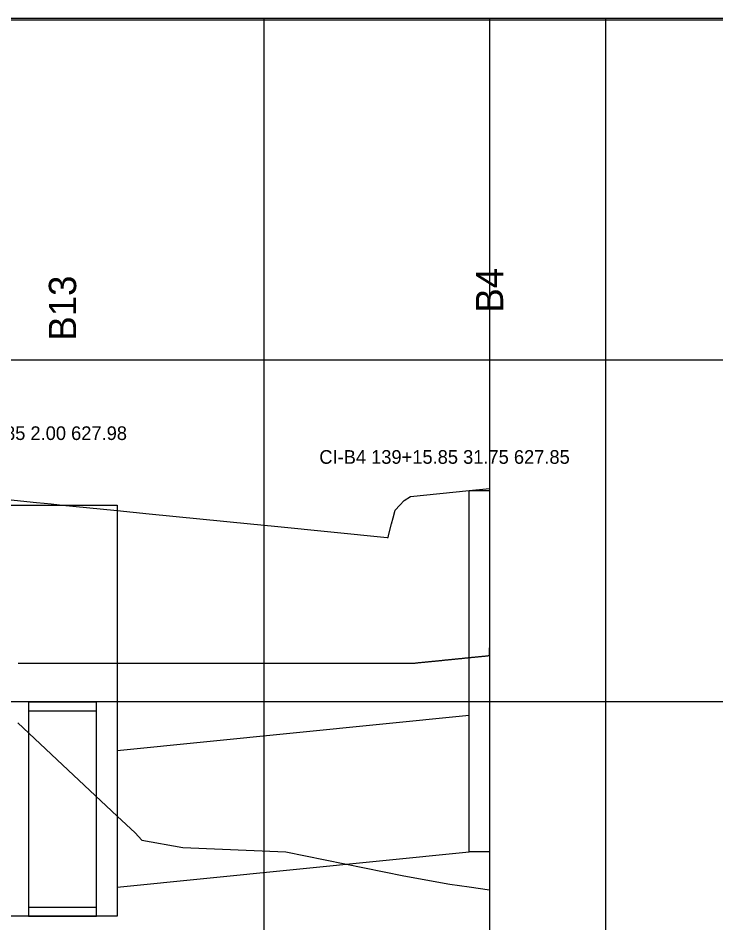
# Model space of a CAD drawing. Extents: x 2253035 to 2279930, y 13774972 to 13793443.
# Drawn here: x 2276981.4 to 2277032.5, y 13792726.4 to 13792792.6 of the extents above; entities that cross this region are included whole.
import ezdxf

# ---------------------------------------------------------------- set-up
doc = ezdxf.new("R2010")
doc.units = 0
for name, color, linetype in [('Default', 7, 'Continuous'), ('E_Utility_ATT_HH', 7, 'Continuous'), ('E_Utility_ATT_PR_PVC', 7, 'Continuous'), ('E_Utility_Telephone_Manhole Telephone_MHT_point', 7, 'Continuous'), ('E_Utility_Telephone_Telephone Pedestal_TPED_Description', 7, 'Continuous'), ('E_Utility_Water_Water Meter_WM_Description', 7, 'Continuous'), ('E_Utillity_Water_Water Line_12in', 7, 'Continuous'), ('E_Utillity_Water_Water Line_1in', 7, 'Continuous'), ('E_Utillity_Water_Water Line_4in', 7, 'Continuous'), ('E_Utillity_Water_Water Line_8in', 7, 'Continuous')]:
    doc.layers.add(name, color=color, linetype=linetype)

msp = doc.modelspace()

# ---------------------------------------------------------------- linework, layer by layer
at = {"layer": 'Default'}
for p, q in [((2276949.404, 13792767.599), (2277015.904, 13792767.599)), ((2276949.404, 13792742.599), (2277015.904, 13792742.599))]:
    msp.add_line(p, q, dxfattribs=at)
msp.add_lwpolyline([(2276949.404, 13792692.599), (2276949.404, 13792792.599), (2277015.904, 13792792.599), (2277015.904, 13792692.599)], close=True, dxfattribs=at)
at = {"layer": 'E_Utility_ATT_PR_PVC'}
msp.add_line((2276984.654, 13792745.405), (2276984.654, 13792745.405), dxfattribs=at)
for points in [[(2276984.654, 13792745.405), (2276984.705, 13792745.405), (2276984.755, 13792745.405), (2276984.805, 13792745.405), (2276984.855, 13792745.405), (2276984.905, 13792745.405), (2276984.955, 13792745.405), (2276985.005, 13792745.405), (2276985.055, 13792745.405), (2276985.105, 13792745.405), (2276985.155, 13792745.405), (2276985.206, 13792745.405), (2276985.256, 13792745.405), (2276985.306, 13792745.405), (2276985.356, 13792745.405), (2276985.406, 13792745.406), (2276985.456, 13792745.406), (2276985.506, 13792745.406), (2276985.556, 13792745.406), (2276985.606, 13792745.406), (2276985.657, 13792745.406), (2276985.707, 13792745.406), (2276985.757, 13792745.406), (2276985.807, 13792745.406), (2276985.857, 13792745.406), (2276985.907, 13792745.406), (2276985.957, 13792745.406), (2276986.007, 13792745.406), (2276986.057, 13792745.406), (2276986.108, 13792745.406), (2276986.158, 13792745.406), (2276986.208, 13792745.406), (2276986.258, 13792745.406), (2276986.308, 13792745.406), (2276986.358, 13792745.406), (2276986.408, 13792745.406), (2276986.458, 13792745.406), (2276986.508, 13792745.406), (2276986.559, 13792745.406), (2276986.609, 13792745.406), (2276986.659, 13792745.406), (2276986.709, 13792745.406), (2276986.759, 13792745.406), (2276986.809, 13792745.406), (2276986.859, 13792745.406), (2276986.909, 13792745.406), (2276986.959, 13792745.406), (2276987.01, 13792745.406), (2276987.06, 13792745.406), (2276987.11, 13792745.406), (2276987.16, 13792745.406), (2276987.21, 13792745.406), (2276987.26, 13792745.406), (2276987.31, 13792745.406), (2276987.36, 13792745.406), (2276987.41, 13792745.406), (2276987.46, 13792745.406), (2276987.511, 13792745.406), (2276987.561, 13792745.406), (2276987.611, 13792745.406), (2276987.661, 13792745.406), (2276987.711, 13792745.406), (2276987.761, 13792745.406), (2276987.811, 13792745.406), (2276987.861, 13792745.406), (2276987.911, 13792745.406), (2276987.962, 13792745.406), (2276988.012, 13792745.406), (2276988.062, 13792745.406), (2276988.112, 13792745.406), (2276988.162, 13792745.406), (2276988.212, 13792745.406), (2276988.262, 13792745.406), (2276988.312, 13792745.406), (2276988.362, 13792745.406), (2276988.413, 13792745.406), (2276988.463, 13792745.406), (2276988.513, 13792745.406), (2276988.563, 13792745.406), (2276988.613, 13792745.406), (2276988.663, 13792745.406), (2276988.713, 13792745.406), (2276988.763, 13792745.406), (2276988.813, 13792745.406), (2276988.864, 13792745.406), (2276988.914, 13792745.406), (2276988.964, 13792745.406), (2276989.014, 13792745.406), (2276989.064, 13792745.406), (2276989.114, 13792745.406), (2276989.164, 13792745.406), (2276989.214, 13792745.406), (2276989.264, 13792745.406), (2276989.315, 13792745.406), (2276989.365, 13792745.406), (2276989.415, 13792745.406), (2276989.465, 13792745.406), (2276989.515, 13792745.406), (2276989.565, 13792745.406), (2276989.615, 13792745.406), (2276989.665, 13792745.406), (2276989.715, 13792745.406), (2276989.765, 13792745.406), (2276989.816, 13792745.406), (2276989.866, 13792745.406), (2276989.916, 13792745.406), (2276989.966, 13792745.407), (2276990.016, 13792745.407), (2276990.066, 13792745.407), (2276990.116, 13792745.407), (2276990.166, 13792745.407), (2276990.216, 13792745.407), (2276990.267, 13792745.407), (2276990.317, 13792745.407), (2276990.367, 13792745.407), (2276990.417, 13792745.407), (2276990.467, 13792745.407), (2276990.517, 13792745.407), (2276990.567, 13792745.407), (2276990.617, 13792745.407), (2276990.667, 13792745.407), (2276990.718, 13792745.407), (2276990.768, 13792745.407), (2276990.818, 13792745.407), (2276990.868, 13792745.407), (2276990.918, 13792745.407), (2276990.968, 13792745.407), (2276991.018, 13792745.407), (2276991.068, 13792745.407), (2276991.118, 13792745.407), (2276991.169, 13792745.407), (2276991.219, 13792745.407), (2276991.269, 13792745.407), (2276991.319, 13792745.407), (2276991.369, 13792745.407), (2276991.419, 13792745.407), (2276991.469, 13792745.407), (2276991.519, 13792745.407), (2276991.569, 13792745.407), (2276991.62, 13792745.407), (2276991.67, 13792745.407), (2276991.72, 13792745.407), (2276991.77, 13792745.407), (2276991.82, 13792745.407), (2276991.87, 13792745.407), (2276991.92, 13792745.407), (2276991.97, 13792745.407), (2276992.02, 13792745.407), (2276992.071, 13792745.407), (2276992.121, 13792745.407), (2276992.171, 13792745.407), (2276992.221, 13792745.407), (2276992.271, 13792745.407), (2276992.321, 13792745.407), (2276992.371, 13792745.407), (2276992.421, 13792745.407), (2276992.471, 13792745.407), (2276992.521, 13792745.407), (2276992.572, 13792745.407), (2276992.622, 13792745.407), (2276992.672, 13792745.407), (2276992.722, 13792745.407), (2276992.772, 13792745.407), (2276992.822, 13792745.407), (2276992.872, 13792745.407), (2276992.922, 13792745.407), (2276992.972, 13792745.407), (2276993.023, 13792745.407), (2276993.073, 13792745.407), (2276993.123, 13792745.407), (2276993.173, 13792745.407), (2276993.223, 13792745.407), (2276993.273, 13792745.407), (2276993.323, 13792745.407), (2276993.373, 13792745.407), (2276993.423, 13792745.407), (2276993.474, 13792745.407), (2276993.524, 13792745.407), (2276993.574, 13792745.407), (2276993.624, 13792745.407), (2276993.674, 13792745.407), (2276993.724, 13792745.407), (2276993.774, 13792745.407), (2276993.824, 13792745.407), (2276993.874, 13792745.407), (2276993.925, 13792745.407), (2276993.975, 13792745.407), (2276994.025, 13792745.407), (2276994.075, 13792745.407), (2276994.125, 13792745.407), (2276994.175, 13792745.407), (2276994.225, 13792745.407), (2276994.275, 13792745.407), (2276994.325, 13792745.407), (2276994.376, 13792745.407), (2276994.426, 13792745.407), (2276994.476, 13792745.407), (2276994.526, 13792745.407), (2276994.576, 13792745.408), (2276994.626, 13792745.408), (2276994.676, 13792745.408), (2276994.726, 13792745.408), (2276994.776, 13792745.408), (2276994.826, 13792745.408), (2276994.877, 13792745.408), (2276994.927, 13792745.408), (2276994.977, 13792745.408), (2276995.027, 13792745.408), (2276995.077, 13792745.408), (2276995.127, 13792745.408), (2276995.177, 13792745.408), (2276995.227, 13792745.408), (2276995.277, 13792745.408), (2276995.328, 13792745.408), (2276995.378, 13792745.408), (2276995.428, 13792745.408), (2276995.478, 13792745.408), (2276995.528, 13792745.408), (2276995.578, 13792745.408), (2276995.628, 13792745.408), (2276995.678, 13792745.408), (2276995.728, 13792745.408), (2276995.779, 13792745.408), (2276995.829, 13792745.408), (2276995.879, 13792745.408), (2276995.929, 13792745.408), (2276995.979, 13792745.408), (2276996.029, 13792745.408), (2276996.079, 13792745.408), (2276996.129, 13792745.408), (2276996.179, 13792745.408), (2276996.23, 13792745.408), (2276996.28, 13792745.408), (2276996.33, 13792745.408), (2276996.38, 13792745.408), (2276996.43, 13792745.408), (2276996.48, 13792745.408), (2276996.53, 13792745.408), (2276996.58, 13792745.408), (2276996.63, 13792745.408), (2276996.681, 13792745.408), (2276996.731, 13792745.408), (2276996.781, 13792745.408), (2276996.831, 13792745.408), (2276996.881, 13792745.408), (2276996.931, 13792745.408), (2276996.981, 13792745.408), (2276997.031, 13792745.408), (2276997.081, 13792745.408), (2276997.132, 13792745.408), (2276997.182, 13792745.408), (2276997.232, 13792745.408), (2276997.282, 13792745.408), (2276997.332, 13792745.408), (2276997.382, 13792745.408), (2276997.432, 13792745.408), (2276997.482, 13792745.408), (2276997.532, 13792745.408), (2276997.582, 13792745.408), (2276997.633, 13792745.408), (2276997.683, 13792745.408), (2276997.733, 13792745.408), (2276997.783, 13792745.408), (2276997.833, 13792745.408), (2276997.883, 13792745.408), (2276997.933, 13792745.408), (2276997.983, 13792745.408), (2276998.033, 13792745.408), (2276998.084, 13792745.408), (2276998.134, 13792745.408), (2276998.184, 13792745.408), (2276998.234, 13792745.408), (2276998.284, 13792745.408), (2276998.334, 13792745.408), (2276998.384, 13792745.408), (2276998.434, 13792745.408), (2276998.484, 13792745.408), (2276998.535, 13792745.408), (2276998.585, 13792745.408), (2276998.635, 13792745.408), (2276998.685, 13792745.408), (2276998.735, 13792745.408), (2276998.785, 13792745.408), (2276998.835, 13792745.408), (2276998.885, 13792745.408), (2276998.935, 13792745.408), (2276998.986, 13792745.408), (2276999.036, 13792745.408), (2276999.086, 13792745.408), (2276999.136, 13792745.409), (2276999.186, 13792745.409), (2276999.236, 13792745.409), (2276999.286, 13792745.409), (2276999.336, 13792745.409), (2276999.386, 13792745.409), (2276999.437, 13792745.409), (2276999.487, 13792745.409), (2276999.537, 13792745.409), (2276999.587, 13792745.409), (2276999.637, 13792745.409), (2276999.687, 13792745.409), (2276999.737, 13792745.409), (2276999.787, 13792745.409), (2276999.837, 13792745.409), (2276999.887, 13792745.409), (2276999.938, 13792745.409), (2276999.988, 13792745.409), (2277000.038, 13792745.409), (2277000.088, 13792745.409), (2277000.138, 13792745.409), (2277000.188, 13792745.409), (2277000.238, 13792745.409), (2277000.288, 13792745.409), (2277000.338, 13792745.409), (2277000.389, 13792745.409), (2277000.439, 13792745.409), (2277000.489, 13792745.409), (2277000.539, 13792745.409), (2277000.589, 13792745.409), (2277000.639, 13792745.409), (2277000.689, 13792745.409), (2277000.739, 13792745.409), (2277000.789, 13792745.409), (2277000.84, 13792745.409), (2277000.89, 13792745.409), (2277000.94, 13792745.409), (2277000.99, 13792745.409), (2277001.04, 13792745.409), (2277001.09, 13792745.409), (2277001.14, 13792745.409), (2277001.19, 13792745.409), (2277001.24, 13792745.409), (2277001.291, 13792745.409), (2277001.341, 13792745.409), (2277001.391, 13792745.409), (2277001.441, 13792745.409), (2277001.491, 13792745.409), (2277001.541, 13792745.409), (2277001.591, 13792745.409), (2277001.641, 13792745.409), (2277001.691, 13792745.409), (2277001.742, 13792745.409), (2277001.792, 13792745.409), (2277001.842, 13792745.409), (2277001.892, 13792745.409), (2277001.942, 13792745.409), (2277001.992, 13792745.409), (2277002.042, 13792745.409), (2277002.092, 13792745.409), (2277002.142, 13792745.409), (2277002.193, 13792745.409), (2277002.243, 13792745.409), (2277002.293, 13792745.409), (2277002.343, 13792745.409), (2277002.393, 13792745.409), (2277002.443, 13792745.409), (2277002.493, 13792745.409), (2277002.543, 13792745.409), (2277002.593, 13792745.409), (2277002.643, 13792745.409), (2277002.694, 13792745.409), (2277002.744, 13792745.409), (2277002.794, 13792745.409), (2277002.844, 13792745.409), (2277002.894, 13792745.409), (2277002.944, 13792745.409), (2277002.994, 13792745.409), (2277003.044, 13792745.409), (2277003.094, 13792745.409), (2277003.145, 13792745.409), (2277003.195, 13792745.409), (2277003.245, 13792745.409), (2277003.295, 13792745.409), (2277003.345, 13792745.409), (2277003.395, 13792745.409), (2277003.445, 13792745.409), (2277003.495, 13792745.409), (2277003.545, 13792745.409), (2277003.596, 13792745.409), (2277003.646, 13792745.409), (2277003.696, 13792745.409), (2277003.746, 13792745.41), (2277003.796, 13792745.41), (2277003.846, 13792745.41), (2277003.896, 13792745.41), (2277003.946, 13792745.41), (2277003.996, 13792745.41), (2277004.047, 13792745.41), (2277004.097, 13792745.41), (2277004.147, 13792745.41), (2277004.197, 13792745.41), (2277004.247, 13792745.41), (2277004.297, 13792745.41), (2277004.347, 13792745.41), (2277004.397, 13792745.41), (2277004.447, 13792745.41), (2277004.498, 13792745.41), (2277004.548, 13792745.41), (2277004.598, 13792745.41), (2277004.648, 13792745.41), (2277004.698, 13792745.41), (2277004.748, 13792745.41), (2277004.798, 13792745.41), (2277004.848, 13792745.41), (2277004.898, 13792745.41), (2277004.948, 13792745.41), (2277004.999, 13792745.41), (2277005.049, 13792745.41), (2277005.099, 13792745.41), (2277005.149, 13792745.41), (2277005.199, 13792745.41), (2277005.249, 13792745.41), (2277005.299, 13792745.41), (2277005.349, 13792745.41), (2277005.399, 13792745.41), (2277005.45, 13792745.41), (2277005.5, 13792745.41), (2277005.55, 13792745.41), (2277005.6, 13792745.41), (2277005.65, 13792745.41), (2277005.7, 13792745.41), (2277005.75, 13792745.41), (2277005.8, 13792745.41), (2277005.85, 13792745.41), (2277005.901, 13792745.41), (2277005.951, 13792745.41), (2277006.001, 13792745.41), (2277006.051, 13792745.41), (2277006.101, 13792745.41), (2277006.151, 13792745.41), (2277006.201, 13792745.41), (2277006.251, 13792745.41), (2277006.301, 13792745.41), (2277006.352, 13792745.41), (2277006.402, 13792745.41), (2277006.452, 13792745.41), (2277006.502, 13792745.41), (2277006.552, 13792745.41), (2277006.602, 13792745.41), (2277006.652, 13792745.41), (2277006.702, 13792745.41), (2277006.752, 13792745.41), (2277006.803, 13792745.41), (2277006.853, 13792745.41), (2277006.903, 13792745.41), (2277006.953, 13792745.41), (2277007.003, 13792745.41), (2277007.053, 13792745.41), (2277007.103, 13792745.41), (2277007.153, 13792745.41), (2277007.203, 13792745.41), (2277007.254, 13792745.41), (2277007.304, 13792745.41), (2277007.354, 13792745.41), (2277007.404, 13792745.41), (2277007.454, 13792745.41), (2277007.504, 13792745.41), (2277007.554, 13792745.41), (2277007.604, 13792745.41), (2277007.654, 13792745.41), (2277007.704, 13792745.41), (2277007.755, 13792745.41), (2277007.805, 13792745.41), (2277007.855, 13792745.41), (2277007.905, 13792745.41), (2277007.955, 13792745.41), (2277008.005, 13792745.41), (2277008.055, 13792745.41), (2277008.105, 13792745.41), (2277008.155, 13792745.41), (2277008.206, 13792745.41), (2277008.256, 13792745.41), (2277008.306, 13792745.41), (2277008.356, 13792745.411), (2277008.406, 13792745.411), (2277008.456, 13792745.411), (2277008.506, 13792745.411), (2277008.556, 13792745.411), (2277008.606, 13792745.411), (2277008.657, 13792745.411), (2277008.707, 13792745.411), (2277008.757, 13792745.411), (2277008.807, 13792745.411), (2277008.857, 13792745.411), (2277008.907, 13792745.411), (2277008.957, 13792745.411), (2277009.007, 13792745.411), (2277009.057, 13792745.411), (2277009.108, 13792745.411), (2277009.158, 13792745.411), (2277009.208, 13792745.411), (2277009.258, 13792745.411), (2277009.308, 13792745.411), (2277009.358, 13792745.411), (2277009.408, 13792745.411), (2277009.458, 13792745.411), (2277009.508, 13792745.411), (2277009.559, 13792745.411), (2277009.609, 13792745.411), (2277009.659, 13792745.411), (2277009.709, 13792745.411), (2277009.759, 13792745.411), (2277009.809, 13792745.411), (2277009.859, 13792745.411), (2277009.909, 13792745.411), (2277009.959, 13792745.411), (2277010.009, 13792745.411), (2277010.06, 13792745.411), (2277010.11, 13792745.411), (2277010.16, 13792745.411), (2277010.21, 13792745.411), (2277010.26, 13792745.411), (2277010.31, 13792745.411), (2277010.36, 13792745.411), (2277010.41, 13792745.412), (2277010.46, 13792745.417), (2277010.511, 13792745.422), (2277010.561, 13792745.427), (2277010.611, 13792745.432), (2277010.661, 13792745.437), (2277010.711, 13792745.442), (2277010.761, 13792745.447), (2277010.811, 13792745.452), (2277010.861, 13792745.457), (2277010.911, 13792745.462), (2277010.962, 13792745.467), (2277011.012, 13792745.472), (2277011.062, 13792745.477), (2277011.112, 13792745.482), (2277011.162, 13792745.487), (2277011.212, 13792745.492), (2277011.262, 13792745.497), (2277011.312, 13792745.502), (2277011.362, 13792745.507), (2277011.413, 13792745.512), (2277011.463, 13792745.517), (2277011.513, 13792745.522), (2277011.563, 13792745.527), (2277011.613, 13792745.532), (2277011.663, 13792745.537), (2277011.713, 13792745.542), (2277011.763, 13792745.547), (2277011.813, 13792745.552), (2277011.864, 13792745.557), (2277011.914, 13792745.562), (2277011.964, 13792745.567), (2277012.014, 13792745.572), (2277012.064, 13792745.577), (2277012.114, 13792745.582), (2277012.164, 13792745.587), (2277012.214, 13792745.592), (2277012.264, 13792745.597), (2277012.314, 13792745.602), (2277012.365, 13792745.607), (2277012.415, 13792745.612), (2277012.465, 13792745.617), (2277012.515, 13792745.622), (2277012.565, 13792745.627), (2277012.615, 13792745.633), (2277012.665, 13792745.638), (2277012.715, 13792745.643), (2277012.765, 13792745.648), (2277012.816, 13792745.653), (2277012.866, 13792745.658), (2277012.916, 13792745.663), (2277012.966, 13792745.668), (2277013.016, 13792745.673), (2277013.066, 13792745.678), (2277013.116, 13792745.683), (2277013.166, 13792745.688), (2277013.216, 13792745.693), (2277013.267, 13792745.698), (2277013.317, 13792745.703), (2277013.367, 13792745.708), (2277013.417, 13792745.713), (2277013.467, 13792745.718), (2277013.517, 13792745.723), (2277013.567, 13792745.728), (2277013.617, 13792745.733), (2277013.667, 13792745.738), (2277013.718, 13792745.743), (2277013.768, 13792745.748), (2277013.818, 13792745.753), (2277013.868, 13792745.758), (2277013.918, 13792745.763), (2277013.968, 13792745.768), (2277014.018, 13792745.773), (2277014.068, 13792745.778), (2277014.118, 13792745.783), (2277014.169, 13792745.788), (2277014.219, 13792745.793), (2277014.269, 13792745.798), (2277014.319, 13792745.803), (2277014.369, 13792745.808), (2277014.419, 13792745.813), (2277014.469, 13792745.818), (2277014.519, 13792745.823), (2277014.569, 13792745.828), (2277014.62, 13792745.833), (2277014.67, 13792745.838), (2277014.72, 13792745.843), (2277014.77, 13792745.848), (2277014.82, 13792745.853), (2277014.87, 13792745.858), (2277014.92, 13792745.864), (2277014.97, 13792745.869), (2277015.02, 13792745.874), (2277015.07, 13792745.879), (2277015.121, 13792745.884), (2277015.171, 13792745.889), (2277015.221, 13792745.894), (2277015.271, 13792745.899), (2277015.321, 13792745.904), (2277015.371, 13792745.909), (2277015.421, 13792745.914), (2277015.471, 13792745.919), (2277015.521, 13792745.924), (2277015.572, 13792745.929), (2277015.622, 13792745.934), (2277015.672, 13792745.939), (2277015.722, 13792745.944), (2277015.772, 13792745.949), (2277015.822, 13792745.954), (2277015.872, 13792745.959), (2277015.904, 13792745.96), (2277015.904, 13792746.533)], [(2276981.401, 13792745.406), (2276981.451, 13792745.406), (2276981.501, 13792745.406), (2276981.551, 13792745.406), (2276981.601, 13792745.406), (2276981.651, 13792745.406), (2276981.701, 13792745.406), (2276981.751, 13792745.406), (2276981.801, 13792745.406), (2276981.851, 13792745.406), (2276981.901, 13792745.406), (2276981.951, 13792745.406), (2276982.001, 13792745.406), (2276982.051, 13792745.406), (2276982.101, 13792745.406), (2276982.151, 13792745.406), (2276982.202, 13792745.406), (2276982.252, 13792745.406), (2276982.302, 13792745.406), (2276982.352, 13792745.406), (2276982.402, 13792745.406), (2276982.452, 13792745.406), (2276982.502, 13792745.406), (2276982.552, 13792745.406), (2276982.602, 13792745.406), (2276982.652, 13792745.406), (2276982.702, 13792745.406), (2276982.752, 13792745.406), (2276982.802, 13792745.406), (2276982.852, 13792745.406), (2276982.902, 13792745.406), (2276982.952, 13792745.406), (2276983.002, 13792745.406), (2276983.053, 13792745.406), (2276983.103, 13792745.406), (2276983.153, 13792745.406), (2276983.203, 13792745.406), (2276983.253, 13792745.406), (2276983.303, 13792745.406), (2276983.353, 13792745.405), (2276983.403, 13792745.405), (2276983.453, 13792745.405), (2276983.503, 13792745.405), (2276983.553, 13792745.405), (2276983.603, 13792745.405), (2276983.653, 13792745.405), (2276983.703, 13792745.405), (2276983.753, 13792745.405), (2276983.803, 13792745.405), (2276983.853, 13792745.405), (2276983.904, 13792745.405), (2276983.954, 13792745.405), (2276984.004, 13792745.405), (2276984.054, 13792745.405), (2276984.104, 13792745.405), (2276984.154, 13792745.405), (2276984.204, 13792745.405), (2276984.254, 13792745.405), (2276984.304, 13792745.405), (2276984.354, 13792745.405), (2276984.404, 13792745.405), (2276984.454, 13792745.405), (2276984.504, 13792745.405), (2276984.554, 13792745.405), (2276984.604, 13792745.405), (2276984.654, 13792745.405)]]:
    msp.add_lwpolyline(points, dxfattribs=at)
at = {"layer": 'E_Utility_Telephone_Manhole Telephone_MHT_point'}
for p, q in [((2276749.404, 13792792.599), (2277074.404, 13792792.599)), ((2276999.404, 13792492.599), (2276999.404, 13792792.599)), ((2277024.404, 13792492.599), (2277024.404, 13792792.599)), ((2276749.404, 13792767.599), (2277074.404, 13792767.599)), ((2276749.404, 13792742.599), (2277074.404, 13792742.599))]:
    msp.add_line(p, q, dxfattribs=at)
at = {"layer": 'E_Utility_Water_Water Meter_WM_Description'}
msp.add_lwpolyline([(2277133.026, 13792792.439), (2276749.404, 13792792.439), (2276749.404, 13792491.266), (2277133.026, 13792491.266)], close=True, dxfattribs=at)
at = {"layer": 'E_Utillity_Water_Water Line_12in'}
for points in [[(2277014.404, 13792758.027), (2277015.904, 13792758.027), (2277015.904, 13792731.599), (2277014.404, 13792731.599)], [(2276980.654, 13792756.975), (2276988.654, 13792756.975), (2276988.654, 13792726.899), (2276980.654, 13792726.899)]]:
    msp.add_lwpolyline(points, close=True, dxfattribs=at)
at = {"layer": 'E_Utillity_Water_Water Line_1in'}
msp.add_lwpolyline([(2276981.383, 13792741.039), (2276984.654, 13792737.969), (2276984.654, 13792737.969), (2276988.654, 13792734.215), (2276988.654, 13792734.215), (2276989.963, 13792732.986), (2276990.47, 13792732.459), (2276993.471, 13792731.908), (2277000.996, 13792731.592), (2277009.632, 13792729.857), (2277012.998, 13792729.245), (2277014.404, 13792729.043), (2277014.404, 13792729.043), (2277015.904, 13792728.827)], dxfattribs=at)
at = {"layer": 'E_Utillity_Water_Water Line_4in'}
for p, q in [((2276988.654, 13792739.024), (2277014.404, 13792741.599)), ((2276988.654, 13792729.024), (2277014.404, 13792731.599))]:
    msp.add_line(p, q, dxfattribs=at)
for points in [[(2276982.154, 13792727.547), (2276987.154, 13792727.547), (2276987.154, 13792742.547), (2276982.154, 13792742.547)], [(2276982.154, 13792726.899), (2276987.154, 13792726.899), (2276987.154, 13792741.899), (2276982.154, 13792741.899)]]:
    msp.add_lwpolyline(points, close=True, dxfattribs=at)
at = {"layer": 'E_Utillity_Water_Water Line_8in'}
msp.add_lwpolyline([(2276980.654, 13792757.374), (2276982.743, 13792757.166), (2276983.316, 13792757.108), (2276983.818, 13792757.058), (2276984.654, 13792756.975), (2276984.654, 13792756.975), (2276988.412, 13792756.599), (2276988.654, 13792756.574), (2276988.654, 13792756.574), (2276990.994, 13792756.34), (2276998.412, 13792755.599), (2277000.165, 13792755.423), (2277008.412, 13792754.599), (2277008.476, 13792754.599), (2277008.506, 13792754.718), (2277008.539, 13792754.844), (2277008.733, 13792755.599), (2277008.844, 13792756.032), (2277008.99, 13792756.599), (2277009.341, 13792756.969), (2277009.656, 13792757.302), (2277010.12, 13792757.599), (2277014.404, 13792758.027), (2277014.404, 13792758.027), (2277015.904, 13792758.177)], dxfattribs=at)

# ---------------------------------------------------------------- texts
at = {"layer": 'E_Utility_ATT_HH'}
for s, p in [('B4', (2277016.904, 13792771.052)), ('B13', (2276985.654, 13792769))]:
    msp.add_text(s, height=2, rotation=90, dxfattribs=at).set_placement(p)
at = {"layer": 'E_Utility_Telephone_Telephone Pedestal_TPED_Description'}
for s, p in [('MH-B13 139+15.85 2.00 627.98', (2276970.303, 13792761.731)), ('CI-B4 139+15.85 31.75 627.85', (2277003.448, 13792759.991))]:
    msp.add_text(s, height=1, rotation=0, dxfattribs=at).set_placement(p)

doc.saveas('drawing.dxf')
